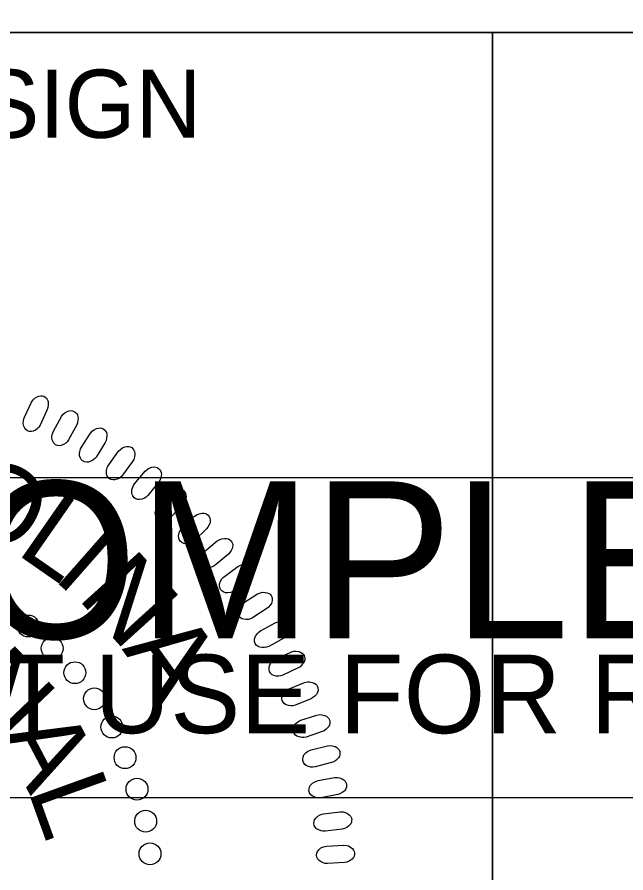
# Model space of a CAD drawing. Extents: x 505602 to 507286, y 483109 to 484209.
# Drawn here: x 507134.2 to 507178.9, y 484097 to 484159.8 of the extents above; entities that cross this region are included whole.
import ezdxf

# ---------------------------------------------------------------- set-up
doc = ezdxf.new("R2010")
doc.units = 0
for name, color, linetype in [('Sheet PE Seal Cell', 7, 'Continuous'), ('Sheet Profile CELL', 7, 'Continuous'), ('Sheet Sticker Incomplete CELL', 7, 'Continuous')]:
    doc.layers.add(name, color=color, linetype=linetype)

msp = doc.modelspace()

# ---------------------------------------------------------------- linework, layer by layer
at = {"layer": 'Sheet PE Seal Cell'}
for points in [[(507134.756, 484130.424), (507135.278, 484131.534), (507135.405, 484131.716), (507135.512, 484131.82), (507135.686, 484131.926), (507135.821, 484131.984), (507135.956, 484132.008), (507136.068, 484132), (507136.178, 484131.97), (507136.27, 484131.904), (507136.366, 484131.826), (507136.435, 484131.727), (507136.487, 484131.592), (507136.508, 484131.495), (507136.505, 484131.33), (507136.482, 484131.143), (507136.435, 484130.989), (507135.906, 484129.849), (507135.814, 484129.705), (507135.713, 484129.598), (507135.564, 484129.492), (507135.403, 484129.413), (507135.281, 484129.382), (507135.114, 484129.395), (507134.97, 484129.441), (507134.852, 484129.541), (507134.779, 484129.63), (507134.706, 484129.775), (507134.67, 484129.979), (507134.686, 484130.17), (507134.714, 484130.3)], [(507136.88, 484129.409), (507137.471, 484130.483), (507137.609, 484130.657), (507137.722, 484130.755), (507137.902, 484130.849), (507138.04, 484130.898), (507138.177, 484130.914), (507138.288, 484130.899), (507138.396, 484130.862), (507138.485, 484130.79), (507138.575, 484130.707), (507138.638, 484130.604), (507138.682, 484130.466), (507138.695, 484130.367), (507138.683, 484130.204), (507138.648, 484130.018), (507138.591, 484129.867), (507137.992, 484128.763), (507137.89, 484128.625), (507137.784, 484128.524), (507137.629, 484128.428), (507137.462, 484128.359), (507137.339, 484128.336), (507137.173, 484128.359), (507137.032, 484128.414), (507136.92, 484128.521), (507136.852, 484128.615), (507136.789, 484128.764), (507136.766, 484128.97), (507136.794, 484129.16), (507136.83, 484129.288)], [(507138.938, 484128.224), (507139.595, 484129.259), (507139.744, 484129.424), (507139.863, 484129.514), (507140.049, 484129.597), (507140.19, 484129.638), (507140.327, 484129.645), (507140.437, 484129.622), (507140.543, 484129.579), (507140.626, 484129.502), (507140.711, 484129.413), (507140.768, 484129.306), (507140.802, 484129.166), (507140.81, 484129.067), (507140.787, 484128.904), (507140.741, 484128.72), (507140.674, 484128.574), (507140.007, 484127.509), (507139.897, 484127.378), (507139.784, 484127.284), (507139.623, 484127.198), (507139.454, 484127.14), (507139.329, 484127.124), (507139.164, 484127.158), (507139.027, 484127.222), (507138.923, 484127.335), (507138.861, 484127.434), (507138.807, 484127.586), (507138.797, 484127.793), (507138.837, 484127.981), (507138.881, 484128.106)], [(507140.938, 484126.95), (507141.659, 484127.942), (507141.818, 484128.098), (507141.943, 484128.181), (507142.133, 484128.252), (507142.276, 484128.283), (507142.413, 484128.282), (507142.522, 484128.252), (507142.625, 484128.203), (507142.703, 484128.121), (507142.782, 484128.026), (507142.832, 484127.917), (507142.858, 484127.774), (507142.86, 484127.674), (507142.826, 484127.514), (507142.769, 484127.334), (507142.693, 484127.191), (507141.96, 484126.17), (507141.842, 484126.047), (507141.723, 484125.96), (507141.558, 484125.883), (507141.384, 484125.836), (507141.259, 484125.829), (507141.097, 484125.873), (507140.964, 484125.945), (507140.866, 484126.065), (507140.811, 484126.167), (507140.767, 484126.322), (507140.77, 484126.53), (507140.821, 484126.715), (507140.873, 484126.837)], [(507142.832, 484125.534), (507143.614, 484126.479), (507143.783, 484126.624), (507143.912, 484126.699), (507144.107, 484126.758), (507144.251, 484126.781), (507144.389, 484126.77), (507144.495, 484126.734), (507144.594, 484126.678), (507144.668, 484126.592), (507144.741, 484126.492), (507144.783, 484126.379), (507144.8, 484126.236), (507144.796, 484126.136), (507144.751, 484125.978), (507144.683, 484125.801), (507144.599, 484125.664), (507143.804, 484124.692), (507143.678, 484124.575), (507143.554, 484124.496), (507143.384, 484124.431), (507143.208, 484124.394), (507143.082, 484124.394), (507142.923, 484124.448), (507142.795, 484124.529), (507142.705, 484124.655), (507142.657, 484124.76), (507142.623, 484124.918), (507142.639, 484125.124), (507142.701, 484125.306), (507142.761, 484125.425)], [(507144.603, 484124.02), (507145.444, 484124.914), (507145.621, 484125.049), (507145.755, 484125.115), (507145.953, 484125.161), (507146.099, 484125.175), (507146.235, 484125.156), (507146.339, 484125.114), (507146.434, 484125.051), (507146.502, 484124.96), (507146.569, 484124.856), (507146.604, 484124.741), (507146.612, 484124.597), (507146.601, 484124.497), (507146.547, 484124.342), (507146.468, 484124.171), (507146.376, 484124.039), (507145.52, 484123.118), (507145.388, 484123.01), (507145.259, 484122.939), (507145.085, 484122.884), (507144.908, 484122.859), (507144.782, 484122.868), (507144.626, 484122.931), (507144.504, 484123.019), (507144.423, 484123.151), (507144.381, 484123.259), (507144.356, 484123.418), (507144.385, 484123.624), (507144.459, 484123.8), (507144.526, 484123.915)], [(507146.348, 484122.327), (507147.243, 484123.166), (507147.428, 484123.289), (507147.566, 484123.347), (507147.766, 484123.381), (507147.912, 484123.385), (507148.047, 484123.358), (507148.148, 484123.309), (507148.24, 484123.241), (507148.302, 484123.145), (507148.362, 484123.037), (507148.39, 484122.92), (507148.389, 484122.776), (507148.371, 484122.678), (507148.308, 484122.526), (507148.219, 484122.36), (507148.117, 484122.234), (507147.206, 484121.369), (507147.067, 484121.269), (507146.935, 484121.206), (507146.757, 484121.163), (507146.578, 484121.149), (507146.453, 484121.165), (507146.302, 484121.238), (507146.185, 484121.334), (507146.112, 484121.47), (507146.077, 484121.58), (507146.063, 484121.742), (507146.105, 484121.945), (507146.19, 484122.117), (507146.264, 484122.227)], [(507147.96, 484120.58), (507148.905, 484121.362), (507149.099, 484121.473), (507149.24, 484121.522), (507149.441, 484121.543), (507149.588, 484121.538), (507149.721, 484121.503), (507149.818, 484121.447), (507149.906, 484121.374), (507149.961, 484121.275), (507150.014, 484121.163), (507150.035, 484121.044), (507150.025, 484120.9), (507150.001, 484120.803), (507149.929, 484120.656), (507149.829, 484120.496), (507149.72, 484120.377), (507148.756, 484119.571), (507148.611, 484119.48), (507148.475, 484119.425), (507148.295, 484119.393), (507148.116, 484119.39), (507147.992, 484119.414), (507147.846, 484119.497), (507147.736, 484119.6), (507147.671, 484119.74), (507147.643, 484119.853), (507147.639, 484120.014), (507147.693, 484120.214), (507147.789, 484120.381), (507147.87, 484120.486)], [(507149.42, 484118.758), (507150.413, 484119.478), (507150.612, 484119.577), (507150.756, 484119.617), (507150.96, 484119.626), (507151.105, 484119.612), (507151.235, 484119.568), (507151.329, 484119.507), (507151.412, 484119.428), (507151.461, 484119.325), (507151.507, 484119.211), (507151.52, 484119.091), (507151.501, 484118.948), (507151.472, 484118.852), (507151.39, 484118.71), (507151.28, 484118.556), (507151.164, 484118.444), (507150.152, 484117.7), (507150.001, 484117.619), (507149.861, 484117.573), (507149.68, 484117.552), (507149.501, 484117.561), (507149.379, 484117.592), (507149.239, 484117.684), (507149.135, 484117.793), (507149.079, 484117.938), (507149.058, 484118.051), (507149.064, 484118.213), (507149.131, 484118.409), (507149.237, 484118.569), (507149.324, 484118.67)], [(507150.821, 484116.812), (507151.857, 484117.469), (507152.062, 484117.555), (507152.208, 484117.586), (507152.411, 484117.582), (507152.556, 484117.559), (507152.683, 484117.507), (507152.773, 484117.439), (507152.85, 484117.356), (507152.893, 484117.25), (507152.932, 484117.133), (507152.938, 484117.013), (507152.909, 484116.871), (507152.874, 484116.778), (507152.783, 484116.64), (507152.664, 484116.494), (507152.542, 484116.39), (507151.485, 484115.71), (507151.329, 484115.639), (507151.187, 484115.602), (507151.004, 484115.592), (507150.826, 484115.612), (507150.707, 484115.651), (507150.572, 484115.751), (507150.476, 484115.867), (507150.429, 484116.015), (507150.415, 484116.13), (507150.431, 484116.291), (507150.51, 484116.482), (507150.626, 484116.636), (507150.72, 484116.73)], [(507152.082, 484114.762), (507153.157, 484115.353), (507153.367, 484115.425), (507153.515, 484115.447), (507153.717, 484115.431), (507153.86, 484115.398), (507153.984, 484115.338), (507154.07, 484115.265), (507154.141, 484115.177), (507154.178, 484115.069), (507154.209, 484114.95), (507154.207, 484114.83), (507154.17, 484114.69), (507154.129, 484114.599), (507154.03, 484114.468), (507153.901, 484114.329), (507153.773, 484114.232), (507152.675, 484113.621), (507152.515, 484113.559), (507152.371, 484113.531), (507152.188, 484113.533), (507152.012, 484113.564), (507151.895, 484113.61), (507151.767, 484113.719), (507151.678, 484113.841), (507151.641, 484113.991), (507151.634, 484114.107), (507151.66, 484114.266), (507151.751, 484114.453), (507151.876, 484114.598), (507151.976, 484114.687)], [(507153.189, 484112.679), (507154.299, 484113.201), (507154.514, 484113.26), (507154.662, 484113.273), (507154.864, 484113.243), (507155.004, 484113.202), (507155.124, 484113.134), (507155.205, 484113.057), (507155.271, 484112.964), (507155.3, 484112.854), (507155.324, 484112.733), (507155.315, 484112.613), (507155.269, 484112.476), (507155.222, 484112.387), (507155.115, 484112.262), (507154.978, 484112.133), (507154.843, 484112.044), (507153.709, 484111.503), (507153.546, 484111.452), (507153.4, 484111.432), (507153.219, 484111.446), (507153.044, 484111.488), (507152.93, 484111.541), (507152.809, 484111.658), (507152.728, 484111.785), (507152.7, 484111.937), (507152.701, 484112.053), (507152.737, 484112.211), (507152.84, 484112.391), (507152.974, 484112.529), (507153.079, 484112.61)], [(507154.169, 484110.518), (507155.31, 484110.969), (507155.527, 484111.015), (507155.676, 484111.018), (507155.875, 484110.976), (507156.013, 484110.926), (507156.128, 484110.851), (507156.204, 484110.768), (507156.264, 484110.671), (507156.286, 484110.559), (507156.302, 484110.437), (507156.286, 484110.319), (507156.231, 484110.184), (507156.179, 484110.099), (507156.065, 484109.981), (507155.92, 484109.86), (507155.78, 484109.781), (507154.614, 484109.311), (507154.448, 484109.27), (507154.301, 484109.26), (507154.12, 484109.285), (507153.949, 484109.338), (507153.839, 484109.399), (507153.725, 484109.523), (507153.652, 484109.655), (507153.634, 484109.808), (507153.642, 484109.924), (507153.688, 484110.079), (507153.802, 484110.252), (507153.944, 484110.381), (507154.054, 484110.456)], [(507155.042, 484108.204), (507156.21, 484108.582), (507156.43, 484108.614), (507156.579, 484108.608), (507156.775, 484108.553), (507156.909, 484108.495), (507157.02, 484108.413), (507157.09, 484108.326), (507157.143, 484108.225), (507157.159, 484108.113), (507157.168, 484107.99), (507157.143, 484107.872), (507157.08, 484107.741), (507157.023, 484107.66), (507156.901, 484107.549), (507156.749, 484107.437), (507156.604, 484107.366), (507155.411, 484106.971), (507155.243, 484106.941), (507155.097, 484106.941), (507154.918, 484106.976), (507154.75, 484107.039), (507154.644, 484107.108), (507154.538, 484107.238), (507154.473, 484107.374), (507154.465, 484107.529), (507154.48, 484107.644), (507154.536, 484107.796), (507154.66, 484107.961), (507154.81, 484108.081), (507154.924, 484108.15)], [(507155.788, 484106.031), (507156.976, 484106.335), (507157.197, 484106.353), (507157.346, 484106.338), (507157.538, 484106.271), (507157.669, 484106.204), (507157.773, 484106.115), (507157.838, 484106.024), (507157.885, 484105.92), (507157.894, 484105.807), (507157.894, 484105.683), (507157.863, 484105.568), (507157.792, 484105.441), (507157.73, 484105.363), (507157.601, 484105.261), (507157.442, 484105.158), (507157.293, 484105.097), (507156.078, 484104.778), (507155.908, 484104.758), (507155.762, 484104.766), (507155.585, 484104.813), (507155.422, 484104.887), (507155.32, 484104.962), (507155.224, 484105.099), (507155.167, 484105.239), (507155.169, 484105.393), (507155.191, 484105.507), (507155.256, 484105.655), (507155.39, 484105.813), (507155.548, 484105.923), (507155.666, 484105.984)], [(507156.297, 484103.776), (507157.502, 484104.006), (507157.725, 484104.01), (507157.872, 484103.985), (507158.059, 484103.906), (507158.185, 484103.832), (507158.285, 484103.736), (507158.343, 484103.641), (507158.384, 484103.535), (507158.385, 484103.421), (507158.378, 484103.297), (507158.339, 484103.184), (507158.261, 484103.062), (507158.194, 484102.988), (507158.059, 484102.894), (507157.894, 484102.802), (507157.742, 484102.75), (507156.508, 484102.508), (507156.337, 484102.498), (507156.192, 484102.516), (507156.019, 484102.575), (507155.861, 484102.658), (507155.764, 484102.739), (507155.675, 484102.882), (507155.628, 484103.026), (507155.639, 484103.179), (507155.669, 484103.291), (507155.743, 484103.435), (507155.887, 484103.584), (507156.052, 484103.684), (507156.173, 484103.737)], [(507156.695, 484101.337), (507157.913, 484101.49), (507158.135, 484101.481), (507158.28, 484101.447), (507158.462, 484101.356), (507158.584, 484101.274), (507158.677, 484101.173), (507158.729, 484101.074), (507158.763, 484100.965), (507158.757, 484100.851), (507158.742, 484100.729), (507158.696, 484100.617), (507158.61, 484100.501), (507158.539, 484100.432), (507158.398, 484100.346), (507158.228, 484100.264), (507158.072, 484100.222), (507156.826, 484100.058), (507156.655, 484100.059), (507156.511, 484100.086), (507156.342, 484100.155), (507156.189, 484100.249), (507156.098, 484100.335), (507156.018, 484100.483), (507155.981, 484100.63), (507156.002, 484100.783), (507156.038, 484100.893), (507156.121, 484101.031), (507156.274, 484101.171), (507156.444, 484101.26), (507156.569, 484101.306)], [(507156.939, 484098.972), (507158.163, 484099.049), (507158.384, 484099.025), (507158.527, 484098.982), (507158.704, 484098.881), (507158.819, 484098.791), (507158.905, 484098.683), (507158.951, 484098.582), (507158.979, 484098.471), (507158.966, 484098.358), (507158.944, 484098.236), (507158.89, 484098.128), (507158.797, 484098.018), (507158.721, 484097.953), (507158.576, 484097.876), (507158.401, 484097.805), (507158.243, 484097.773), (507156.989, 484097.687), (507156.819, 484097.699), (507156.676, 484097.736), (507156.512, 484097.815), (507156.366, 484097.918), (507156.28, 484098.01), (507156.21, 484098.163), (507156.181, 484098.311), (507156.211, 484098.462), (507156.255, 484098.57), (507156.346, 484098.703), (507156.508, 484098.833), (507156.683, 484098.912), (507156.81, 484098.949)]]:
    msp.add_lwpolyline(points, close=True, dxfattribs=at)
for centre in [(507135.036, 484115.118), (507136.787, 484113.484), (507138.459, 484111.69), (507139.891, 484109.778), (507141.165, 484107.706), (507142.137, 484105.457), (507143.012, 484103.146), (507143.648, 484100.795), (507143.966, 484098.405)]:
    msp.add_circle(centre, 0.801, dxfattribs=at)
at = {"layer": 'Sheet Profile CELL'}
msp.add_line((507169.08, 484158.662), (507169.08, 484046.212), dxfattribs=at)
for points in [[(507069.03, 484183.712), (507269.08, 484183.712), (507269.08, 484158.662), (507069.03, 484158.662)], [(507069.03, 484158.662), (507169.08, 484158.662), (507169.08, 484046.162), (507069.03, 484046.162)], [(507169.08, 484158.662), (507269.08, 484158.662), (507269.08, 484046.162), (507169.08, 484046.162)]]:
    msp.add_lwpolyline(points, close=True, dxfattribs=at)
at = {"layer": 'Sheet Sticker Incomplete CELL'}
msp.add_lwpolyline([(507095.597, 484102.505), (507095.597, 484126.005), (507242.597, 484126.005), (507242.597, 484102.505)], close=True, dxfattribs=at)

# ---------------------------------------------------------------- texts
at = {"layer": 'Sheet PE Seal Cell'}
for s, rotation, p in [('O', 331.63025, (507129.326, 484123.015)), ('L', 325.14089, (507134.059, 484120.484)), ('I', 318.65154, (507136.752, 484118.63)), ('N', 312.16218, (507138.557, 484117.21)), ('A', 305.67282, (507141.877, 484113.43)), ('N', 313.65025, (507129.525, 484110.172)), ('A', 297.77065, (507132.862, 484107.091)), ('L', 289.83086, (507134.985, 484103.097))]:
    msp.add_text(s, height=5.669, rotation=rotation, dxfattribs=at).set_placement(p)
at = {"layer": 'Sheet Profile CELL'}
msp.add_text('ROADWAY DESIGN', height=5.0001, dxfattribs=at).set_placement((507085.692, 484150.924))
at = {"layer": 'Sheet Sticker Incomplete CELL'}
for s, height, p in [('INCOMPLETE PLANS', 11.52, (507104.547, 484114.205)), ('DO NOT USE FOR R/W ACQUISITION', 5.76, (507107.797, 484107.255))]:
    msp.add_text(s, height=height, dxfattribs=at).set_placement(p)

doc.saveas('drawing.dxf')
